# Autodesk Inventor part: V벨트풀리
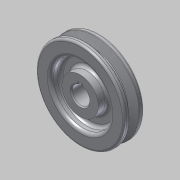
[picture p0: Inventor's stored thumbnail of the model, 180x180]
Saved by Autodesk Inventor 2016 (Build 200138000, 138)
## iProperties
Created: 2018-11
Part Number: V벨트풀리
Material: 알루미늄 6061
Document SubType Name: Modeling
Designer: mduedu
Density: 1 g/cm^3
Appearance: 알루미늄 - 평지
Author: mduedu
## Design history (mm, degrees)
sketch "스케치1"
  geometry: L1 (-9.5, 0)-(9.5, 0); L2 (9.5, 0)-(9.5, 42.7); L3 (9.5, 42.7)-(-9.5, 42.7); L4 (-9.5, 42.7)-(-9.5, 0); L5 (-4.877, 42.7)-(-1.953, 33.7); L6 (-1.953, 33.7)-(1.953, 33.7); L7 (1.953, 33.7)-(4.877, 42.7); L8 (0, 0)-(0, 42.7); L9 (-9.5, 40)-(9.5, 40); 3 further points
  constraints: 18 end point, 8 point on line, 3 perpendicular, 2 midpoint, 2 parallel, 1 coincident, 1 horizontal, 1 other
  dimensions: "d0" = 85.4 diameter of L3 L1; "d2" = 19 distance of L2.end L3.end; "d3" = 80 diameter of L9 L1; "d4" = 36 deg angle of L7 L5; "d5" = 6.3 distance between parallel lines of L6 L9; "d6" = 8 distance of point (4, 40) point (-4, 40)
revolve "회전1" sketch "스케치1" stored, may be unused: angle "d7" = 90 deg
sketch "스케치2"
  geometry: L1 (-2.5, 8.124)-(2.5, 8.124); L2 (2.5, 8.124)-(2.5, 10.8); L3 (2.5, 10.8)-(-2.5, 10.8); L4 (-2.5, 10.8)-(-2.5, 8.124); A1 r 8.5 centre (0, 0) between (-2.5, 8.124) and (2.5, 8.124); 1 further point
  constraints: 8 end point, 2 parallel, 2 point on circle, 1 centre point, 1 coincident, 1 horizontal, 1 perpendicular
  dimensions: "d8" = 17 diameter of A1; "d10" = 19.3 dimension on A1 L3; "d11" = 5 distance of L2.end L3.end
extrude "돌출1" cut sketch "스케치2" stored distance "d12" = 10; taper "d13" = 0 deg
chamfer "모따기1" distance "d14" = 1; stored, may be unused: second distance "d15" = 2, angle "d16" = 45 deg
fillet "모깎기1" dims "d17" = 1, "d18" = 0.5, "d19" = 2
sketch "스케치3"
  geometry: C1 r 17.5 at (0, 0); C2 r 28.5 at (0, 0); 1 further point
  constraints: 2 centre point, 2 coincident
  dimensions: "d20" = 35 diameter of C1; "d23" = 57 diameter of C2
extrude "돌출2" cut sketch "스케치3" distance "d24" = 9.5; taper "d25" = 0 deg
fillet "모깎기2" dims "d26" = 3
node "솔리드1"
